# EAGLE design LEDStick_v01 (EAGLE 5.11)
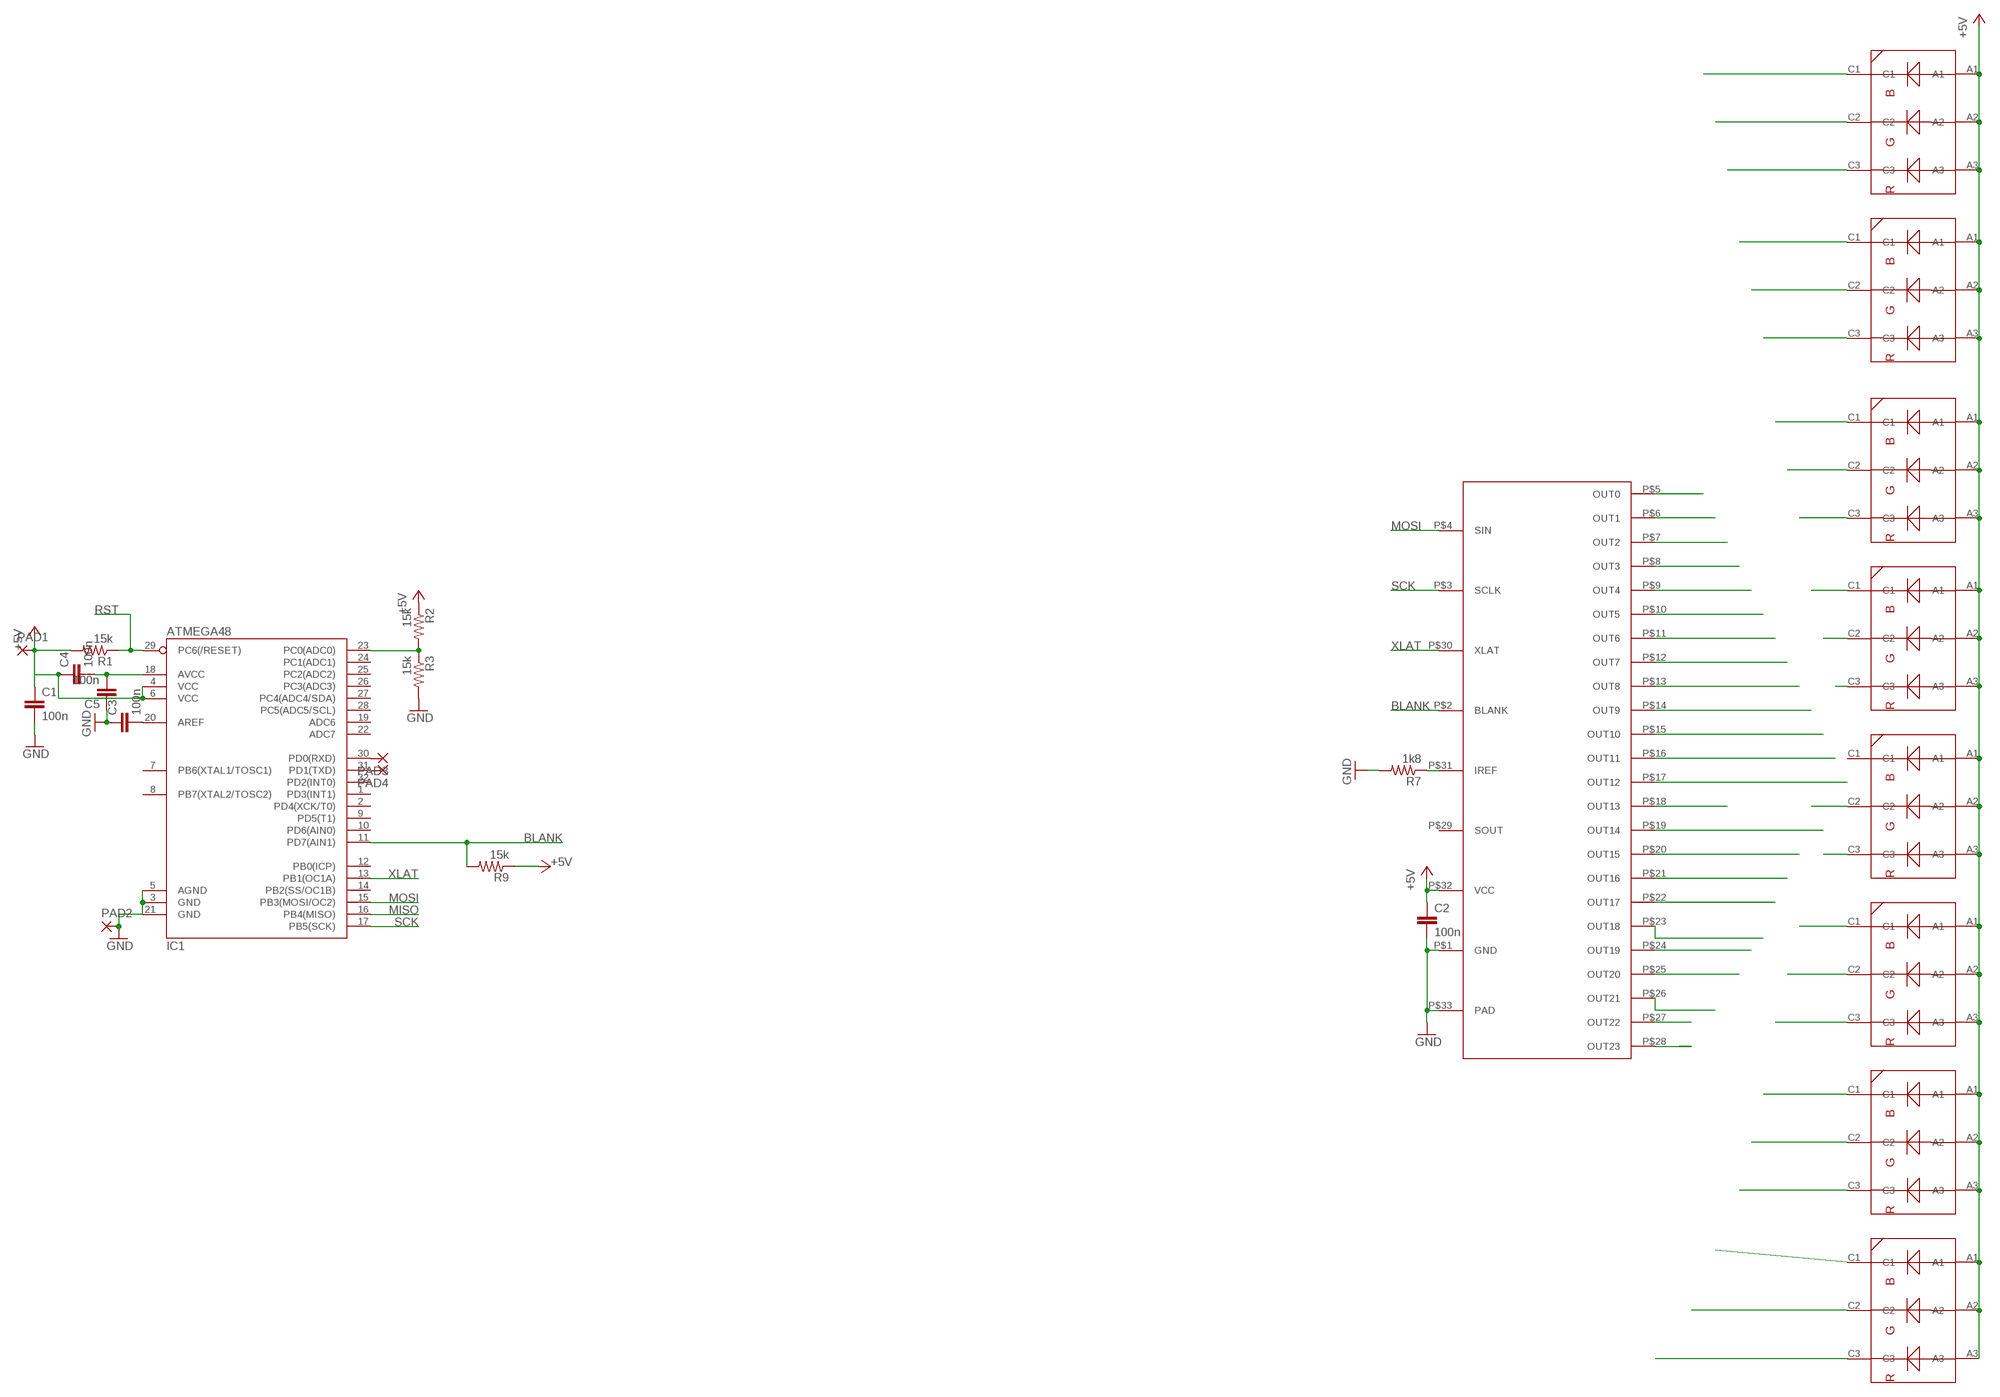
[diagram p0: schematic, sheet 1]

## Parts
C1  100n  CAP0805  [0805]
C2  100n  CAP0805  [0805]
C3  100n  CAP0805  [0805]
C4  100n  CAP0805  [0805]
C5  100n  CAP0805  [0805]
IC1  ATMEGA48  ATMEGA168  [TQFP32-08]
IC2  TLC5947  [HTSSOP32_DAP]
PAD1  SMD5  [SMD2,54-5,08]
PAD2  SMD5  [SMD2,54-5,08]
PAD3  SMD5  [SMD2,54-5,08]
PAD4  SMD5  [SMD2,54-5,08]
R1  15k  RESISTOR  [0805]
R2  15k  RESISTOR  [0805]
R3  15k  RESISTOR  [0805]
R7  1k8  RESISTOR  [0805]
R9  15k  RESISTOR  [0805]
U$1  OSRAM_LRTB_GFTGSMALL  [PLCC-6_SMALL]
U$2  OSRAM_LRTB_GFTGSMALL  [PLCC-6_SMALL]
U$3  OSRAM_LRTB_GFTGSMALL  [PLCC-6_SMALL]
U$4  OSRAM_LRTB_GFTGSMALL  [PLCC-6_SMALL]
U$5  OSRAM_LRTB_GFTGSMALL  [PLCC-6_SMALL]
U$6  OSRAM_LRTB_GFTGSMALL  [PLCC-6_SMALL]
U$7  OSRAM_LRTB_GFTGSMALL  [PLCC-6_SMALL]
U$8  OSRAM_LRTB_GFTGSMALL  [PLCC-6_SMALL]

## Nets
+5V: C1.1 C2.1 C4.1 IC1.4(VCC) IC1.6(VCC) IC2.P$32(VCC) PAD1.1(P) R1.2 R2.1 R9.1 U$1.A1 U$1.A2 U$1.A3 U$2.A1 U$2.A2 U$2.A3 U$3.A1 U$3.A2 U$3.A3 U$4.A1 U$4.A2 U$4.A3 U$5.A1 U$5.A2 U$5.A3 U$6.A1 U$6.A2 U$6.A3 U$7.A1 U$7.A2 U$7.A3 U$8.A1 U$8.A2 U$8.A3
BLANK: IC1.11(PD7(AIN1)) IC2.P$2(BLANK) R9.2
GND: C1.2 C2.2 C3.1 C5.1 IC1.3(GND) IC1.5(AGND) IC1.21(GND) IC2.P$1(GND) IC2.P$33(PAD) PAD2.1(P) R3.2 R7.2
MISO: IC1.16(PB4(MISO))
MOSI: IC1.15(PB3(MOSI/OC2)) IC2.P$4(SIN)
N$1: U$1.C3
N$2: U$1.C2
N$3: U$1.C1
N$4: U$2.C3
N$5: IC2.P$24(OUT19)
N$6: IC2.P$23(OUT18)
N$7: IC2.P$22(OUT17)
N$8: IC2.P$21(OUT16)
N$9: IC2.P$20(OUT15)
N$10: IC2.P$19(OUT14)
N$11: IC2.P$18(OUT13)
N$12: IC2.P$31(IREF) R7.1
N$13: IC2.P$17(OUT12)
N$14: IC2.P$16(OUT11)
N$15: IC2.P$15(OUT10)
N$16: IC2.P$14(OUT9)
N$17: IC2.P$13(OUT8)
N$18: IC2.P$12(OUT7)
N$19: IC2.P$11(OUT6)
N$20: IC2.P$10(OUT5)
N$21: U$7.C2
N$22: U$7.C1
N$23: U$8.C3
N$24: U$8.C2
N$25: U$8.C1
N$26: IC2.P$27(OUT22)
N$27: IC2.P$26(OUT21)
N$28: IC2.P$25(OUT20)
N$29: U$2.C2
N$30: C3.2 IC1.20(AREF)
N$31: U$2.C1
N$32: IC1.23(PC0(ADC0)) R2.2 R3.1
N$33: U$3.C3
N$34: U$3.C2
N$35: U$3.C1
N$36: U$4.C3
N$37: U$5.C3
N$38: U$5.C2
N$39: U$5.C1
N$40: U$6.C3
N$41: U$6.C2
N$42: U$6.C1
N$43: U$7.C3
N$44: IC2.P$9(OUT4)
N$45: IC2.P$8(OUT3)
N$46: IC2.P$7(OUT2)
N$47: IC2.P$6(OUT1)
N$48: IC2.P$5(OUT0)
N$49: U$4.C2
N$50: IC2.P$28(OUT23)
N$52: C4.2 C5.2 IC1.18(AVCC)
N$53: IC1.30(PD0(RXD)) PAD3.1(P)
N$54: IC1.31(PD1(TXD)) PAD4.1(P)
RST: IC1.29(PC6(/RESET)) R1.1
SCK: IC1.17(PB5(SCK)) IC2.P$3(SCLK)
XLAT: IC1.13(PB1(OC1A)) IC2.P$30(XLAT)
Unconnected: IC1.1(PD3(INT1)) IC1.2(PD4(XCK/T0)) IC1.7(PB6(XTAL1/TOSC1)) IC1.8(PB7(XTAL2/TOSC2)) IC1.9(PD5(T1)) IC1.10(PD6(AIN0)) IC1.12(PB0(ICP)) IC1.14(PB2(SS/OC1B)) IC1.19(ADC6) IC1.22(ADC7) IC1.24(PC1(ADC1)) IC1.25(PC2(ADC2)) IC1.26(PC3(ADC3)) IC1.27(PC4(ADC4/SDA)) IC1.28(PC5(ADC5/SCL)) IC1.32(PD2(INT0)) IC2.P$29(SOUT) U$4.C1

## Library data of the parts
C1-C5 = SparkFun:CAP: Capacitor
IC1 = SparkFun:ATMEGA168
IC2 = tlc5947:TLC5947
PAD1-PAD4 = wirepad:SMD5: SMD PAD
R1-R3 R7 R9 = SparkFun:RESISTOR: Resistor
U$1-U$8 = seb:OSRAM_LRTB_GFTG

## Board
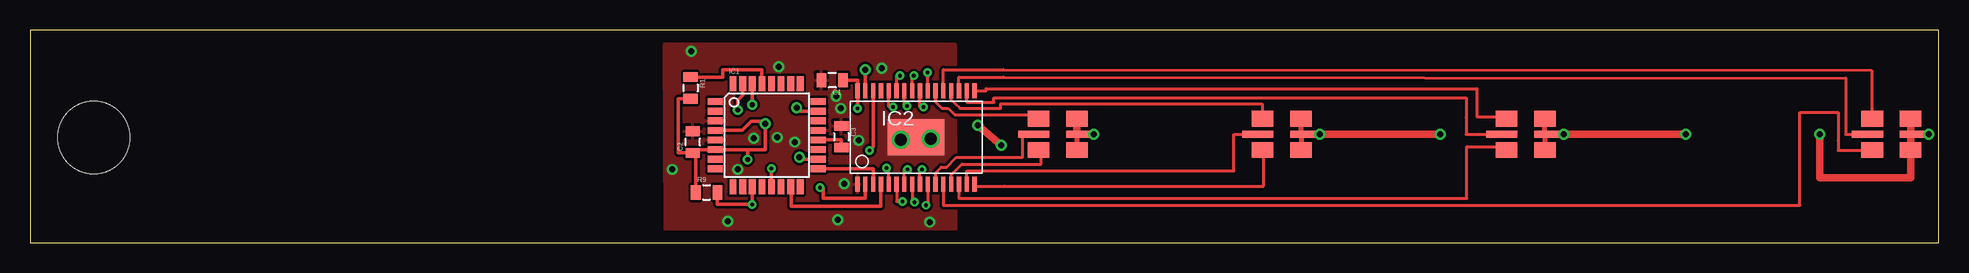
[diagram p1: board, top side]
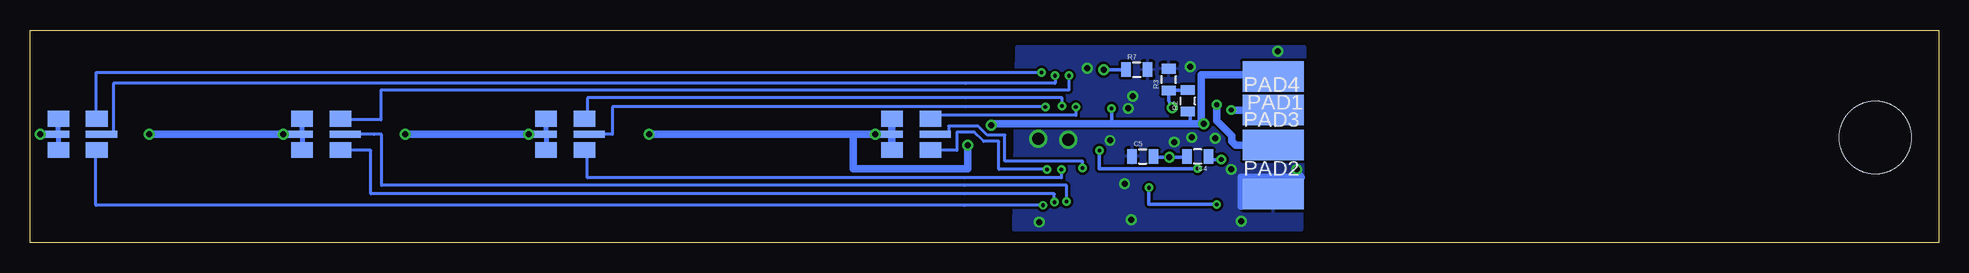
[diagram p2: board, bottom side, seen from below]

Size 159.08 x 17.72 mm. Coordinates in mm from the lower left corner, seen from the top.
Outline: 0,0 159.08,0 159.08,17.72 0,17.72 0,0
Copper layers (1*16): Top 0.035mm / dielectric 1.5mm / Bottom 0.035mm
Design rules "default *": minimum track width 10mil, minimum drill 0.3mm, track to track 8mil, track to pad 8mil, pad to pad 8mil, via to via 8mil, smd to smd 8mil, copper to edge 15mil, drill to drill 8mil, minimum pad ring 10mil, minimum via ring 8mil, stop-mask expansion 4mil, vias tented up to drill 50mil, thermal gap 10mil
Holes 6 mm at 5.32,8.76

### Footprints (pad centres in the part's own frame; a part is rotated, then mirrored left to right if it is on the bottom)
0805 = smd 0.8 x 1.2: 1 -0.9,0; 2 0.9,0
TQFP32-08 = smd 1.27 x 0.559: 1 -4.293,2.8; 2 -4.293,2; 3 -4.293,1.2; 4 -4.293,0.4; 5 -4.293,-0.4; 6 -4.293,-1.2; 7 -4.293,-2; 8 -4.293,-2.8; 17 4.293,-2.8; 18 4.293,-2; 19 4.293,-1.2; 20 4.293,-0.4; 21 4.293,0.4; 22 4.293,1.2; 23 4.293,2; 24 4.293,2.8 | smd 0.559 x 1.27: 9 -2.8,-4.293; 10 -2,-4.293; 11 -1.2,-4.293; 12 -0.4,-4.293; 13 0.4,-4.293; 14 1.2,-4.293; 15 2,-4.293; 16 2.8,-4.293; 25 2.8,4.293; 26 2,4.293; 27 1.2,4.293; 28 0.4,4.293; 29 -0.4,4.293; 30 -1.2,4.293; 31 -2,4.293; 32 -2.8,4.293
HTSSOP32_DAP = smd 0.356 x 1.27: P$1 -4.875,-3.9; P$2 -4.225,-3.9; P$3 -3.575,-3.9; P$4 -2.925,-3.9; P$5 -2.275,-3.9; P$6 -1.625,-3.9; P$7 -0.975,-3.9; P$8 -0.325,-3.9; P$9 0.325,-3.9; P$10 0.975,-3.9; P$11 1.625,-3.9; P$12 2.275,-3.9; P$13 2.925,-3.9; P$14 3.575,-3.9; P$15 4.225,-3.9; P$16 4.875,-3.9; P$17 4.875,3.9; P$18 4.225,3.9; P$19 3.575,3.9; P$20 2.925,3.9; P$21 2.275,3.9; P$22 1.625,3.9; P$23 0.975,3.9; P$24 0.325,3.9; P$25 -0.325,3.9; P$26 -0.975,3.9; P$27 -1.625,3.9; P$28 -2.275,3.9; P$29 -2.925,3.9; P$30 -3.575,3.9; P$31 -4.225,3.9; P$32 -4.875,3.9 | smd 4.698 x 3: P$33 0,0
SMD2,54-5,08 = smd 2.54 x 5.08: 1 0,0
PLCC-6_SMALL = smd 1.3 x 1.8: A1 1.3,-1.6; A3 -1.3,-1.6; C1 1.3,1.6; C3 -1.3,1.6 | smd 0.6 x 2.6: A2 0,-2; C2 0,2

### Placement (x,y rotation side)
C1  66.85,13.53 180 top
C2  55.23,8.38 90 top
C3  67.61,8.83 270 top
C4  61.77,7.18 180 bottom
C5  66.34,7.18 0 bottom
IC1  61.39,8.95 0 top
IC2  73.84,8.76 0 top
PAD1  55.49,13.84 90 bottom
PAD2  55.49,4.06 270 bottom
PAD3  55.49,8.13 270 bottom
PAD4  55.49,11.05 270 bottom
R1  55.04,12.89 270 top
R2  62.6,11.81 90 bottom
R3  64.19,13.59 90 bottom
R7  66.85,14.41 0 bottom
R9  56.38,4.19 0 top
U$1  155.12,9.02 270 bottom
U$2  124.64,9.02 90 top
U$3  85.65,9.02 270 bottom
U$4  85.65,9.02 90 top
U$5  104.32,9.02 90 top
U$6  114.48,9.02 270 bottom
U$7  155.12,9.02 90 top
U$8  134.8,9.02 270 bottom

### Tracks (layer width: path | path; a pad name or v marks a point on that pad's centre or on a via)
+5V  (via drill 0.3, 0.4, 0.5)
  Top 0.305: v68.95,11.18 68.96,11.18 IC2.P$32 68.96,13.53 C1.1 | 59.68,7.75 IC1.6 55.23,7.75 C2.1 | 59.68,7.75 60.82,7.75 61.26,7.75 61.26,8.95 61.26,9.35 61.26,10.1 | R9.1 55.47,7.74 C2.1 | R1.2 54.03,12 54.03,7.48 C2.1 | IC1.4 59.36,9.35 60.12,10.1 60.88,10.1 | 61.26,10.1 60.88,10.1 | 61.26,10.1 v61.26,9.91 | 61.26,10.1 60.88,10.1 | v59.8,6.92 59.8,7.75 59.68,7.75
  Top 0.406: 156.72,9.02 U$7.A3 | 156.72,9.02 U$7.A2 156.72,9.02 | U$7.A1 156.72,9.02 | 126.24,9.02 U$2.A1 | 126.24,9.02 U$2.A2 126.24,9.02 | 126.24,9.02 U$2.A3 | 105.92,9.02 U$5.A1 | 105.92,9.02 U$5.A2 105.92,9.02 | 105.92,9.02 U$5.A3 | 87.25,9.02 U$4.A3 | 87.25,9.02 U$4.A2 87.25,9.02 | 87.25,9.02 U$4.A1
  Top 0.61: v117.53,9.02 107.43,9.02 v107.49,9.02 U$5.A2 | v137.97,9.02 126.73,9.02 v127.81,9.02 U$2.A2 | U$7.A2 156.72,9.02 U$7.A2 | U$7.A2 v158.23,9.02 | v149.15,9.02 149.15,5.4 155.56,5.4 156.72,5.4 U$7.A1 | v78.98,9.78 v80.95,8.13 | U$4.A1 87.25,9.02 v88.63,9.02
  Bottom 0.305: 68.95,9.91 v68.95,11.18 | R2.1 62.41,10.91 62.41,9.91 | v61.26,9.91 61.46,10.1 v61.26,9.91 | v61.26,9.91 61.9,9.91 | C4.1 60.87,6.92 v59.8,6.92
  Bottom 0.406: 156.72,9.02 U$7.A3 | 156.72,9.02 U$7.A2 156.72,9.02 | 156.72,9.02 U$7.A1 | 136.4,9.02 U$8.A1 | 136.4,9.02 U$8.A2 136.4,9.02 | 136.4,9.02 U$8.A3 | 116.08,9.02 U$6.A3 | 116.08,9.02 U$6.A2 116.08,9.02 | 116.08,9.02 U$6.A1 | U$4.A1 87.25,9.08 | 87.25,9.08 U$4.A2 87.25,9.08 | U$4.A3 87.25,9.08
  Bottom 0.61: v107.49,9.02 96.89,9.02 97.4,9.02 90.47,9.02 | v117.53,9.02 U$6.A2 | U$6.A2 116.08,9.02 | 116.08,9.02 115.68,9.02 116.08,9.02 | U$6.A2 116.08,9.02 | v117.53,9.02 U$6.A2 | v117.53,9.02 v127.81,9.02 | v149.15,9.02 v137.97,9.02 U$8.A2 | v158.23,9.02 U$7.A2 | v117.53,9.02 U$6.A2 | 90.47,9.02 v88.63,9.02 | v88.63,9.02 U$4.A2 | v78.98,9.78 78.98,9.91 69.2,9.91 68.95,9.91 62.41,9.91 61.9,9.91 v61.26,9.91 61.46,10.1 61.46,13.97 | 61.46,13.97 61.2,13.97 | PAD1.1 55.8,13.97 61.2,13.97 | 61.46,13.97 61.2,13.97 | 61.46,13.97 61.2,13.97 | v80.95,8.13 80.95,7.75 80.95,6.16 90.47,6.16 90.47,9.02 | 87.25,9.02 U$4.A3 U$4.A1 87.25,9.02 | v88.63,9.02 87.25,9.02 | v88.63,9.02 87.25,9.02
BLANK  (via drill 0.3)
  Top 0.305: IC2.P$2 69.61,3.68 66.09,3.68 66.09,4.57 v65.84,4.57 | IC1.11 v60.19,3.17 57.28,3.17 R9.2
  Bottom 0.305: v65.84,4.57 65.84,3.17 v60.19,3.17
GND  (via drill 0.5, 1)
  Bottom 0.61: 58.15,3.05 58.15,5.46 53.14,5.46 53.52,5.84 v53.52,6.1
  other vias: 63.74,8.38 58.98,6.1 67.87,4.89 62.28,8.76 60.31,8.7 70.98,14.54 67.55,11.18 67.17,12.19 72.57,8.57 75.04,8.64 62.41,14.67 69.08,8.51 55.11,15.94 58.15,1.78 67.3,1.9 74.98,1.71
  pour Bottom: 52.82,16.32 76.89,16.32 77.14,1.08 53.07,1.08
  pour Top: 52.88,1.14 77.2,1.14 77.14,16.51 52.82,16.51
MOSI
  Top 0.305: IC2.P$4 70.91,3.05 63.42,3.05 63.42,4.66 IC1.15
N$5  (via drill 0.3)
  Top 0.254: IC2.P$24 74.16,11.3 v74.47,11.3
  Bottom 0.254: v74.47,11.3 81.14,11.3 110.54,11.3 110.54,9.02 112.32,9.02
N$6  (via drill 0.3)
  Top 0.254: IC2.P$23 74.81,13.82 v74.79,14.16
  Bottom 0.254: v74.79,14.16 81.14,14.16 153.59,14.16 153.59,10.1
N$7
  Top 0.254: IC2.P$22 75.46,11.71 76,11.18 76.5,11.18 77.08,10.67 83.87,10.67 84.25,10.29
N$8
  Top 0.254: IC2.P$21 76.11,14.42 81.14,14.42 153.47,14.35 153.47,10.22
N$9
  Top 0.254: IC2.P$20 76.76,11.87 77.52,11.18 80.89,11.18 80.89,11.56 102.67,11.56 102.67,10.29
N$10
  Top 0.254: IC2.P$19 77.41,13.78 81.14,13.78 151.31,13.72 151.31,9.02 152.2,9.02
N$11
  Top 0.254: IC2.P$18 78.06,11.68 80.31,11.68 80.31,12.06 119.68,12.06 119.68,10.41 119.68,9.02 121.78,9.02
N$12  (via drill 0.5)
  Top 0.305: v69.61,14.42 IC2.P$31
  Bottom 0.305: R7.1 v69.61,14.42
N$13
  Top 0.254: IC2.P$17 79.65,12.66 79.68,12.64 79.68,12.83 120.57,12.83 120.57,10.48 123.11,10.48
N$14
  Top 0.254: IC2.P$16 78.71,4.7 81.2,4.7 102.79,4.7 102.79,7.75
N$15
  Top 0.254: IC2.P$15 78.06,5.97 81.27,5.97 100.32,5.97 100.32,9.02 101.33,9.02
N$16
  Top 0.254: IC2.P$14 77.41,3.68 81.2,3.68 119.75,3.68 119.75,8 123.18,8
N$17
  Top 0.254: IC2.P$13 76.76,5.66 77.65,6.54 84.25,6.54 84.25,7.68
N$18
  Top 0.254: IC2.P$12 76.11,3.11 81.2,3.11 147.5,3.11 147.5,10.86 150.67,10.86 150.67,8.51 150.67,7.68 153.4,7.68
N$19
  Top 0.254: IC2.P$11 75.46,5.82 75.93,6.29 76.38,6.29 77.2,7.11 82.73,7.11 82.73,9.02 83.17,9.02
N$20  (via drill 0.3)
  Top 0.254: IC2.P$10 74.81,3.11 v74.66,3.11
  Bottom 0.254: v74.66,3.11 81.2,3.11 153.59,3.11 153.59,7.49
N$26  (via drill 0.3)
  Top 0.254: IC2.P$27 72.21,13.91 v72.5,13.91
  Bottom 0.254: v72.5,13.91 72.5,12.7 81.14,12.7 129.84,12.7 129.84,10.22 132.45,10.22 132.45,10.29
N$27  (via drill 0.3)
  Top 0.254: IC2.P$26 72.86,11.37 v73.08,11.37
  Bottom 0.254: v73.08,11.37 73.08,12.06 81.14,12.06 112.64,12.06 112.64,10.35
N$28  (via drill 0.3)
  Top 0.254: IC2.P$25 73.51,13.91 v73.65,13.91
  Bottom 0.254: v73.65,13.91 73.65,13.27 81.14,13.27 152.13,13.27 152.13,9.02 153.53,9.02
N$30
  Top 0.305: IC1.20 67.6,8.55 C3.2
N$32  (via drill 0.5)
  Top 0.305: IC1.23 63.88,10.95 v63.88,11.24
  Bottom 0.305: v63.88,11.24 64.19,11.81 R3.1 63.99,12.71 R2.2
N$44  (via drill 0.3)
  Top 0.254: IC2.P$9 74.16,6.1 v74.35,6.1
  Bottom 0.254: v74.35,6.1 78.35,6.1 78.35,8.45 79.62,8.45 79.68,8.51 80.38,9.21 81.84,9.21 81.84,8.45 81.84,7.68 83.68,7.68
N$45  (via drill 0.3)
  Top 0.254: IC2.P$8 73.51,3.37 v73.71,3.37
  Bottom 0.254: v73.71,3.37 73.71,4.06 81.2,4.06 130.67,4.06 130.67,7.68 132.64,7.68 132.64,7.62
N$46  (via drill 0.3)
  Top 0.254: IC2.P$7 72.86,6.1 v73.14,6.1
  Bottom 0.254: v73.14,6.1 73.14,5.4 81.2,5.4 112.64,5.4 112.64,7.62
N$47  (via drill 0.3)
  Top 0.254: IC2.P$6 72.21,3.43 v72.69,3.43
  Bottom 0.254: v72.69,3.43 72.69,4.76 81.2,4.76 129.78,4.76 129.78,9.02 130.42,9.02 132,9.02
N$48  (via drill 0.3)
  Top 0.254: IC2.P$5 71.56,6.22 v71.36,6.22
  Bottom 0.254: v71.36,6.22 71.36,6.79 77.84,6.79 77.84,8.95 79.3,8.95 80.06,9.72 82.54,9.72 82.54,8.95 83.24,8.95
N$50  (via drill 0.3)
  Top 0.254: IC2.P$28 71.56,11.3 v71.93,11.3
  Bottom 0.254: v71.93,11.3 71.93,10.6 83.68,10.6 83.68,9.97 83.43,9.97
N$52  (via drill 0.5)
  Top 0.305: v64.12,7.11 64.12,6.95 IC1.18
  Bottom 0.305: C4.2 62.67,7.11 v64.12,7.11 65.44,7.11 C5.2
N$53  (via drill 0.4)
  Top 0.305: IC1.30 v60.19,11.49
  Bottom 0.61: v60.19,11.49 60.19,10.16 58.91,8.89 58.91,8.45 58.6,8.13 PAD3.1
N$54  (via drill 0.4)
  Top 0.305: IC1.31 59.39,12.29 58.98,11.87 v58.98,11.05
  Bottom 0.61: PAD4.1 v58.98,11.05
RST
  Top 0.305: IC1.29 60.99,14.42 57.71,14.42 57.71,13.79 R1.1
SCK
  Top 0.305: IC2.P$3 70.26,6.15 IC1.17
XLAT  (via drill 0.3)
  Top 0.305: IC2.P$30 70.26,8 v69.96,7.68 | v61.77,6.16 61.77,4.66 IC1.13
  Bottom 0.305: v69.96,7.68 69.96,6.16 v61.77,6.16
